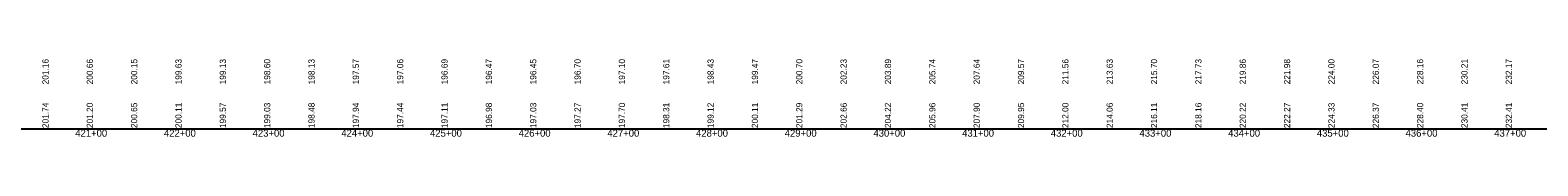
# Model space of a CAD drawing. Extents: x 1876258 to 1926563, y 729739 to 834437.
# Drawn here: x 1920391 to 1922091, y 830495 to 830583 of the extents above; entities that cross this region are included whole.
import ezdxf

# ---------------------------------------------------------------- set-up
doc = ezdxf.new("R2010")
doc.units = 0
for name, color, linetype in [('RD_EX_RailRoad', 7, 'Continuous'), ('RD_PD_ALT3_CL', 7, 'Continuous'), ('RD_PD_Final_Cl', 7, 'Continuous')]:
    doc.layers.add(name, color=color, linetype=linetype)

msp = doc.modelspace()

# ---------------------------------------------------------------- linework, layer by layer
at = {"layer": 'RD_PD_Final_Cl'}
msp.add_line((1878363.1, 830504.3), (1926563.1, 830504.3), dxfattribs=at)

# ---------------------------------------------------------------- texts
at = {"layer": 'RD_EX_RailRoad'}
for s, p in [('201.16', (1920412.1, 830554.3)), ('200.66', (1920462.1, 830554.3)), ('200.15', (1920512.1, 830554.3)), ('199.63', (1920562.1, 830554.3)), ('199.13', (1920612.1, 830554.3)), ('198.60', (1920662.1, 830554.3)), ('198.13', (1920712.1, 830554.3)), ('197.57', (1920762.1, 830554.3)), ('197.06', (1920812.1, 830554.3)), ('196.69', (1920862.1, 830554.3)), ('196.47', (1920912.1, 830554.3)), ('196.45', (1920962.1, 830554.3)), ('196.70', (1921012.1, 830554.3)), ('197.10', (1921062.1, 830554.3)), ('197.61', (1921112.1, 830554.3)), ('198.43', (1921162.1, 830554.3)), ('199.47', (1921212.1, 830554.3)), ('200.70', (1921262.1, 830554.3)), ('202.23', (1921312.1, 830554.3)), ('203.89', (1921362.1, 830554.3)), ('205.74', (1921412.1, 830554.3)), ('207.64', (1921462.1, 830554.3)), ('209.57', (1921512.1, 830554.3)), ('211.56', (1921562.1, 830554.3)), ('213.63', (1921612.1, 830554.3)), ('215.70', (1921662.1, 830554.3)), ('217.73', (1921712.1, 830554.3)), ('219.86', (1921762.1, 830554.3)), ('221.98', (1921812.1, 830554.3)), ('224.00', (1921862.1, 830554.3)), ('226.07', (1921912.1, 830554.3)), ('228.16', (1921962.1, 830554.3)), ('230.21', (1922012.1, 830554.3)), ('232.17', (1922062.1, 830554.3)), ('201.74', (1920412.1, 830505)), ('201.20', (1920462.1, 830505)), ('200.65', (1920512.1, 830505)), ('200.11', (1920562.1, 830505)), ('199.57', (1920612.1, 830505)), ('199.03', (1920662.1, 830505)), ('198.48', (1920712.1, 830505)), ('197.94', (1920762.1, 830505)), ('197.44', (1920812.1, 830505)), ('197.11', (1920862.1, 830505)), ('196.98', (1920912.1, 830505)), ('197.03', (1920962.1, 830505)), ('197.27', (1921012.1, 830505)), ('197.70', (1921062.1, 830505)), ('198.31', (1921112.1, 830505)), ('199.12', (1921162.1, 830505)), ('200.11', (1921212.1, 830505)), ('201.29', (1921262.1, 830505)), ('202.66', (1921312.1, 830505)), ('204.22', (1921362.1, 830505)), ('205.96', (1921412.1, 830505)), ('207.90', (1921462.1, 830505)), ('209.95', (1921512.1, 830505)), ('212.00', (1921562.1, 830505)), ('214.06', (1921612.1, 830505)), ('216.11', (1921662.1, 830505)), ('218.16', (1921712.1, 830505)), ('220.22', (1921762.1, 830505)), ('222.27', (1921812.1, 830505)), ('224.33', (1921862.1, 830505)), ('226.37', (1921912.1, 830505)), ('228.40', (1921962.1, 830505)), ('230.41', (1922012.1, 830505)), ('232.41', (1922062.1, 830505))]:
    msp.add_text(s, height=7, rotation=90, dxfattribs=at).set_placement(p)
at = {"layer": 'RD_PD_ALT3_CL'}
for s, p in [('421+00', (1920442.2, 830495.3)), ('421+00', (1920442.2, 830495.3)), ('422+00', (1920542.2, 830495.3)), ('422+00', (1920542.2, 830495.3)), ('423+00', (1920642.2, 830495.3)), ('423+00', (1920642.2, 830495.3)), ('424+00', (1920742.2, 830495.3)), ('424+00', (1920742.2, 830495.3)), ('425+00', (1920842.2, 830495.3)), ('425+00', (1920842.2, 830495.3)), ('426+00', (1920942.2, 830495.3)), ('426+00', (1920942.2, 830495.3)), ('427+00', (1921042.2, 830495.3)), ('427+00', (1921042.2, 830495.3)), ('428+00', (1921142.2, 830495.3)), ('428+00', (1921142.2, 830495.3)), ('429+00', (1921242.2, 830495.3)), ('429+00', (1921242.2, 830495.3)), ('430+00', (1921342.2, 830495.3)), ('430+00', (1921342.2, 830495.3)), ('431+00', (1921442.2, 830495.3)), ('431+00', (1921442.2, 830495.3)), ('432+00', (1921542.2, 830495.3)), ('432+00', (1921542.2, 830495.3)), ('433+00', (1921642.2, 830495.3)), ('433+00', (1921642.2, 830495.3)), ('434+00', (1921742.2, 830495.3)), ('434+00', (1921742.2, 830495.3)), ('435+00', (1921842.2, 830495.3)), ('435+00', (1921842.2, 830495.3)), ('436+00', (1921942.2, 830495.3)), ('436+00', (1921942.2, 830495.3)), ('437+00', (1922042.2, 830495.3)), ('437+00', (1922042.2, 830495.3))]:
    msp.add_text(s, height=8, dxfattribs=at).set_placement(p)

doc.saveas('drawing.dxf')
